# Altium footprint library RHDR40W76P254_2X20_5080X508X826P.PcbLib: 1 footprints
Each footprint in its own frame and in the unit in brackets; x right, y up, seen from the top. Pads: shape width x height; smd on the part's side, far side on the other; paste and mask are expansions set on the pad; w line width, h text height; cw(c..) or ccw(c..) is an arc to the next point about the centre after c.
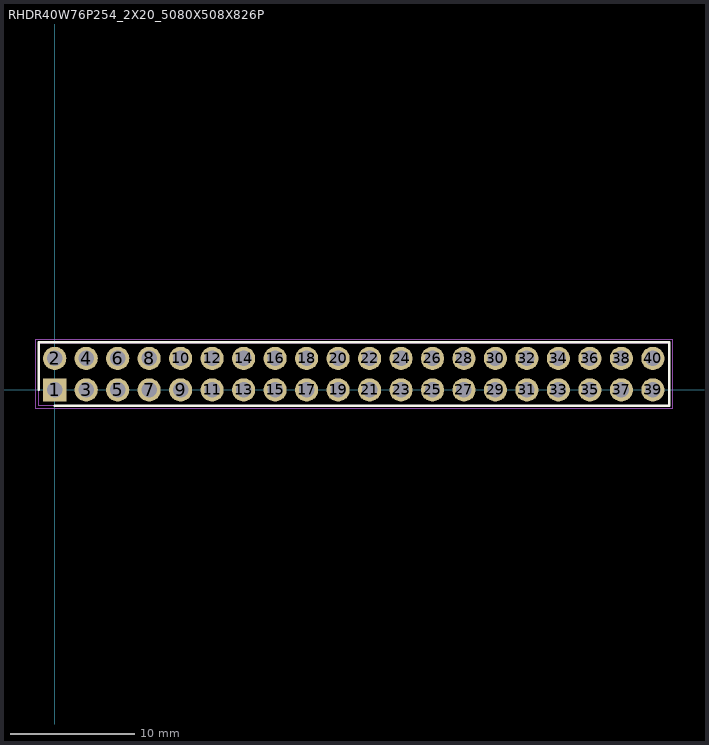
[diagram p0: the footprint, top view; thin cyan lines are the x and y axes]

## RHDR40W76P254_2X20_5080X508X826P [mm]
pads (40):
  rect 1.875x1.875 / inner round 1.875 / far side rect 1.875x1.875 hole 1.25: 1(0,0)
  round 1.875 hole 1.25: 2(0,2.54) 3(2.54,0) 4(2.54,2.54) 5(5.08,0) 6(5.08,2.54) 7(7.62,0) 8(7.62,2.54) 9(10.16,0) 10(10.16,2.54) 11(12.7,0) 12(12.7,2.54) 13(15.24,0) 14(15.24,2.54) 15(17.78,0) 16(17.78,2.54) 17(20.32,0) 18(20.32,2.54) 19(22.86,0) 20(22.86,2.54) 21(25.4,0) 22(25.4,2.54) 23(27.94,0) 24(27.94,2.54) 25(30.48,0) 26(30.48,2.54) 27(33.02,0) 28(33.02,2.54) 29(35.56,0) 30(35.56,2.54) 31(38.1,0) 32(38.1,2.54) 33(40.64,0) 34(40.64,2.54) 35(43.18,0) 36(43.18,2.54) 37(45.72,0) 38(45.72,2.54) 39(48.26,0) 40(48.26,2.54)
Top Overlay:
  lines w0.2: -1.27,0 -1.27,3.845 49.565,3.845 49.565,-1.27 0,-1.27
Mechanical 15:
  lines w0.1: -1.27,-1.27 -1.27,3.81 49.53,3.81 49.53,-1.27 -1.27,-1.27
Mechanical 20:
  lines w0.05: -1.52,-1.52 -1.52,4.095 49.815,4.095 49.815,-1.52 -1.52,-1.52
